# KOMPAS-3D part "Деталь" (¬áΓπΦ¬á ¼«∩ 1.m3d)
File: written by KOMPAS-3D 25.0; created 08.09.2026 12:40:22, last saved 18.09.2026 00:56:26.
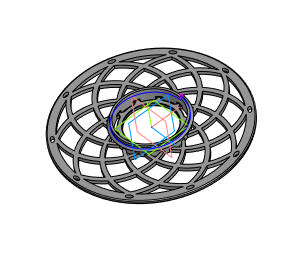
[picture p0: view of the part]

Document properties: Автор: PC; Полное имя файла: C:\Users\PC\Documents\катушка моя 1.m3d

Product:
- Part/product: Деталь
    Масса: 0.365235

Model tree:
1. Эскиз:1
2. Элемент выдавливания:1
     Расстояние 1 = 4
3. Эскиз:2
4. Элемент выдавливания:2
     Расстояние 2 = 10
5. Эскиз:3
6. Элемент выдавливания:3
     Расстояние 2 = 10
7. Эскиз:4
8. Элемент выдавливания:4
     Расстояние 2 = 10
9. Эскиз:5
10. Элемент выдавливания:5
     Расстояние 1 = 15
11. Эскиз:6
12. Спираль:1
     Число витков = 1; Шаг = 6; Высота = 6; Диаметр 1 = 77; Диаметр 2 = 10; Координата Y = 7; Нутация = -90
13. Элемент по траектории:1
     Длина траектории = 241.977
14. Скругление:4
     Радиус = 1
15. Скругление:5
     Радиус = 0.5
16. Скругление:6
     Радиус = 0.5
17. Скругление:7
     Радиус = 1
